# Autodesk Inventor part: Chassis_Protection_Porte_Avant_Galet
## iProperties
Created: 2009-01
Part Number: Chassis_Protection_Porte_Avant_Galet
Material: Nylon - 6/6
Document SubType Name: Modeling
Designer: claivier
Author: claivier
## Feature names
1. Extrusion1
